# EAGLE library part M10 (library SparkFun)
Header 10 Standard 10-pin 0.1" header. Use with straight break away headers (SKU : PType-HD), right angle break away headers (PType-HD-RightAngle), swiss pins (PType-30F), machine pins (PType-MP), and female headers (PType-FH). Molex polarized connector foot print use with SKU : Con-Hdr with associated crimp pins and housings.
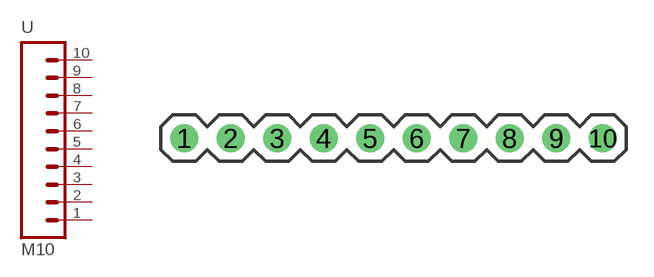
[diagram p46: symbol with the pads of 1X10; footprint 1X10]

Designator prefix -

## M10  [1X10]
1  1  pas
2  2  pas
3  3  pas
4  4  pas
5  5  pas
6  6  pas
7  7  pas
8  8  pas
9  9  pas
10  10  pas

## Footprint 1X10 (pad centres in mm)
drill 1.016 round: 1 0,0; 2 2.54,0; 3 5.08,0; 4 7.62,0; 5 10.16,0; 6 12.7,0; 7 15.24,0; 8 17.78,0; 9 20.32,0; 10 22.86,0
